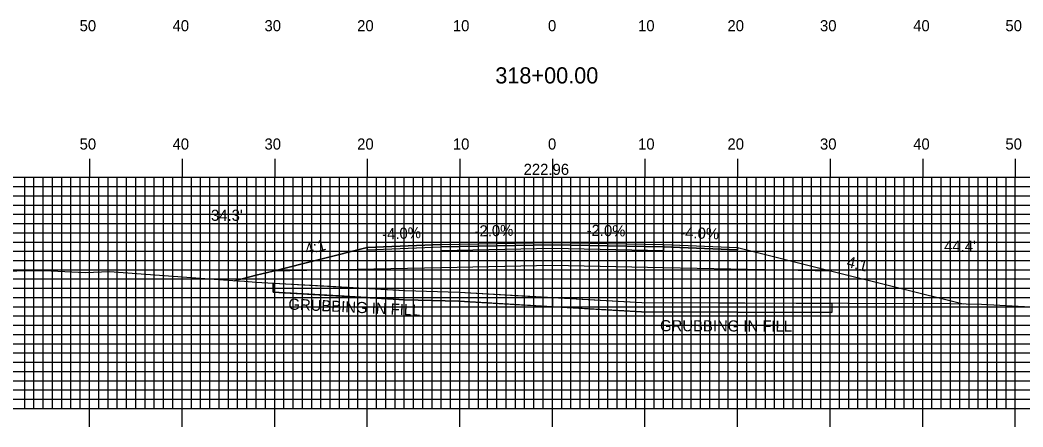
# Model space of a CAD drawing. Extents: x 1819637 to 1819981, y 442591 to 442811.
# Drawn here: x 1819745.7 to 1819854, y 442696.7 to 442740.7 of the extents above; entities that cross this region are included whole.
import ezdxf

# ---------------------------------------------------------------- set-up
doc = ezdxf.new("R2010")
doc.units = 0
for name, color, linetype in [('ANNOTATION', 7, 'Continuous'), ('D_Roadway_Centerline', 7, 'Continuous'), ('D_Roadway_Centerline_Text', 7, 'Continuous'), ('D_Roadway_Edge_Shoulder', 7, 'Continuous'), ('D_Roadway_Edge_TW', 7, 'Continuous'), ('D_Roadway_Pavement', 7, 'Continuous'), ('D_Roadway_SlopeLines', 7, 'Continuous'), ('D_Roadway_SubGrade', 7, 'Continuous'), ('D_Text_Standard', 7, 'Continuous'), ('GRUBBING IN FILL', 7, 'Continuous'), ('H_V ANNOTATION', 7, 'Continuous'), ('MAJOR', 7, 'Continuous'), ('MINOR', 7, 'Continuous'), ('S_Roadway_Centerline', 7, 'Continuous')]:
    doc.layers.add(name, color=color, linetype=linetype)

msp = doc.modelspace()

# ---------------------------------------------------------------- linework, layer by layer
at = {"layer": 'D_Roadway_Centerline'}
msp.add_lwpolyline([(1819768.84, 442712.48), (1819771.18, 442713.07), (1819773, 442713.52), (1819783.18, 442716.07), (1819791.18, 442716.39), (1819803.18, 442716.63), (1819815.18, 442716.39), (1819823.18, 442716.07), (1819833.35, 442713.52), (1819847.56, 442709.97)], dxfattribs=at)
at = {"layer": 'D_Roadway_Edge_Shoulder'}
for points in [[(1819791.18, 442716.39), (1819783.18, 442716.07), (1819783.18, 442715.82), (1819791.18, 442716.14)], [(1819815.18, 442716.39), (1819823.18, 442716.07), (1819823.18, 442715.82), (1819815.18, 442716.14)]]:
    msp.add_lwpolyline(points, close=True, dxfattribs=at)
at = {"layer": 'D_Roadway_Edge_TW'}
msp.add_lwpolyline([(1819791.18, 442716.14), (1819791.18, 442716.39), (1819803.18, 442716.63), (1819815.18, 442716.39), (1819815.18, 442716.14), (1819803.18, 442716.38)], close=True, dxfattribs=at)
at = {"layer": 'D_Roadway_Pavement'}
msp.add_lwpolyline([(1819791.18, 442715.72), (1819791.18, 442716.14), (1819803.18, 442716.38), (1819815.18, 442716.14), (1819815.18, 442715.72), (1819803.18, 442715.96)], close=True, dxfattribs=at)
at = {"layer": 'D_Roadway_SlopeLines'}
for points in [[(1819783.18, 442716.07), (1819773, 442713.52), (1819771.18, 442713.07), (1819768.84, 442712.48)], [(1819823.18, 442716.07), (1819833.35, 442713.52), (1819847.56, 442709.97)]]:
    msp.add_lwpolyline(points, dxfattribs=at)
at = {"layer": 'D_Roadway_SubGrade'}
msp.add_lwpolyline([(1819791.18, 442713.89), (1819773, 442713.52), (1819783.18, 442716.07), (1819783.18, 442715.82), (1819791.18, 442716.14), (1819803.18, 442716.38), (1819815.18, 442716.14), (1819823.18, 442715.82), (1819823.18, 442716.07), (1819833.35, 442713.52), (1819815.18, 442713.89), (1819803.18, 442714.13)], close=True, dxfattribs=at)
at = {"layer": 'GRUBBING IN FILL'}
for p, q in [((1819773, 442712.23), (1819773, 442711.23)), ((1819773, 442712.23), (1819773, 442711.23)), ((1819833.35, 442710.04), (1819833.35, 442709.04)), ((1819833.35, 442710.04), (1819833.35, 442709.04))]:
    msp.add_line(p, q, dxfattribs=at)
for points in [[(1819773, 442711.23), (1819773, 442712.23), (1819779.19, 442711.88), (1819787.25, 442711.42), (1819793.12, 442711.25), (1819802.98, 442710.68), (1819803.18, 442710.67), (1819803.18, 442709.67), (1819793.07, 442710.26), (1819787.21, 442710.42), (1819780.11, 442710.83)], [(1819773, 442711.23), (1819773, 442712.23), (1819779.19, 442711.88), (1819787.25, 442711.42), (1819793.12, 442711.25), (1819802.98, 442710.68), (1819803.18, 442710.67), (1819803.18, 442709.67), (1819793.07, 442710.26), (1819787.21, 442710.42), (1819780.11, 442710.83)], [(1819803.18, 442710.67), (1819812.84, 442710.11), (1819829.52, 442710.05), (1819833.35, 442710.04), (1819833.35, 442709.04), (1819823.08, 442709.08), (1819812.81, 442709.11), (1819803.18, 442709.67)], [(1819803.18, 442710.67), (1819812.84, 442710.11), (1819829.52, 442710.05), (1819833.35, 442710.04), (1819833.35, 442709.04), (1819823.08, 442709.08), (1819812.81, 442709.11), (1819803.18, 442709.67)]]:
    msp.add_lwpolyline(points, close=True, dxfattribs=at)
msp.add_lwpolyline([(1819773, 442711.23), (1819787.21, 442710.42), (1819793.07, 442710.26), (1819812.81, 442709.11), (1819833.35, 442709.04)], dxfattribs=at)
msp.add_lwpolyline([(1819773, 442711.23), (1819787.21, 442710.42), (1819793.07, 442710.26), (1819812.81, 442709.11), (1819833.35, 442709.04)], dxfattribs=at)
at = {"layer": 'MAJOR'}
for p, q in [((1819753.18, 442725.67), (1819753.18, 442723.67)), ((1819763.18, 442725.67), (1819763.18, 442723.67)), ((1819773.18, 442725.67), (1819773.18, 442723.67)), ((1819783.18, 442725.67), (1819783.18, 442723.67)), ((1819793.18, 442725.67), (1819793.18, 442723.67)), ((1819803.18, 442725.67), (1819803.18, 442723.67)), ((1819813.18, 442725.67), (1819813.18, 442723.67)), ((1819823.18, 442725.67), (1819823.18, 442723.67)), ((1819833.18, 442725.67), (1819833.18, 442723.67)), ((1819843.18, 442725.67), (1819843.18, 442723.67)), ((1819853.18, 442725.67), (1819853.18, 442723.67)), ((1819663.18, 442723.67), (1819943.18, 442723.67)), ((1819663.18, 442723.67), (1819943.18, 442723.67)), ((1819753.18, 442698.67), (1819753.18, 442723.67)), ((1819763.18, 442698.67), (1819763.18, 442723.67)), ((1819773.18, 442698.67), (1819773.18, 442723.67)), ((1819783.18, 442698.67), (1819783.18, 442723.67)), ((1819793.18, 442698.67), (1819793.18, 442723.67)), ((1819803.18, 442698.67), (1819803.18, 442723.67)), ((1819813.18, 442698.67), (1819813.18, 442723.67)), ((1819823.18, 442698.67), (1819823.18, 442723.67)), ((1819833.18, 442698.67), (1819833.18, 442723.67)), ((1819843.18, 442698.67), (1819843.18, 442723.67)), ((1819853.18, 442698.67), (1819853.18, 442723.67)), ((1819663.18, 442718.67), (1819943.18, 442718.67)), ((1819663.18, 442713.67), (1819943.18, 442713.67)), ((1819663.18, 442708.67), (1819943.18, 442708.67)), ((1819663.18, 442703.67), (1819943.18, 442703.67)), ((1819663.18, 442698.67), (1819943.18, 442698.67)), ((1819663.18, 442698.67), (1819943.18, 442698.67)), ((1819753.18, 442696.66), (1819753.18, 442698.67)), ((1819763.18, 442696.66), (1819763.18, 442698.67)), ((1819773.18, 442696.66), (1819773.18, 442698.67)), ((1819783.18, 442696.66), (1819783.18, 442698.67)), ((1819793.18, 442696.66), (1819793.18, 442698.67)), ((1819803.18, 442696.66), (1819803.18, 442698.67)), ((1819813.18, 442696.66), (1819813.18, 442698.67)), ((1819823.18, 442696.66), (1819823.18, 442698.67)), ((1819833.18, 442696.66), (1819833.18, 442698.67)), ((1819843.18, 442696.66), (1819843.18, 442698.67)), ((1819853.18, 442696.66), (1819853.18, 442698.67))]:
    msp.add_line(p, q, dxfattribs=at)
at = {"layer": 'MINOR'}
for p, q in [((1819746.18, 442698.67), (1819746.18, 442723.67)), ((1819747.18, 442698.67), (1819747.18, 442723.67)), ((1819748.18, 442698.67), (1819748.18, 442723.67)), ((1819749.18, 442698.67), (1819749.18, 442723.67)), ((1819750.18, 442698.67), (1819750.18, 442723.67)), ((1819751.18, 442698.67), (1819751.18, 442723.67)), ((1819752.18, 442698.67), (1819752.18, 442723.67)), ((1819754.18, 442698.67), (1819754.18, 442723.67)), ((1819755.18, 442698.67), (1819755.18, 442723.67)), ((1819756.18, 442698.67), (1819756.18, 442723.67)), ((1819757.18, 442698.67), (1819757.18, 442723.67)), ((1819758.18, 442698.67), (1819758.18, 442723.67)), ((1819759.18, 442698.67), (1819759.18, 442723.67)), ((1819760.18, 442698.67), (1819760.18, 442723.67)), ((1819761.18, 442698.67), (1819761.18, 442723.67)), ((1819762.18, 442698.67), (1819762.18, 442723.67)), ((1819764.18, 442698.67), (1819764.18, 442723.67)), ((1819765.18, 442698.67), (1819765.18, 442723.67)), ((1819766.18, 442698.67), (1819766.18, 442723.67)), ((1819767.18, 442698.67), (1819767.18, 442723.67)), ((1819768.18, 442698.67), (1819768.18, 442723.67)), ((1819769.18, 442698.67), (1819769.18, 442723.67)), ((1819770.18, 442698.67), (1819770.18, 442723.67)), ((1819771.18, 442698.67), (1819771.18, 442723.67)), ((1819772.18, 442698.67), (1819772.18, 442723.67)), ((1819774.18, 442698.67), (1819774.18, 442723.67)), ((1819775.18, 442698.67), (1819775.18, 442723.67)), ((1819776.18, 442698.67), (1819776.18, 442723.67)), ((1819777.18, 442698.67), (1819777.18, 442723.67)), ((1819778.18, 442698.67), (1819778.18, 442723.67)), ((1819779.18, 442698.67), (1819779.18, 442723.67)), ((1819780.18, 442698.67), (1819780.18, 442723.67)), ((1819781.18, 442698.67), (1819781.18, 442723.67)), ((1819782.18, 442698.67), (1819782.18, 442723.67)), ((1819784.18, 442698.67), (1819784.18, 442723.67)), ((1819785.18, 442698.67), (1819785.18, 442723.67)), ((1819786.18, 442698.67), (1819786.18, 442723.67)), ((1819787.18, 442698.67), (1819787.18, 442723.67)), ((1819788.18, 442698.67), (1819788.18, 442723.67)), ((1819789.18, 442698.67), (1819789.18, 442723.67)), ((1819790.18, 442698.67), (1819790.18, 442723.67)), ((1819791.18, 442698.67), (1819791.18, 442723.67)), ((1819792.18, 442698.67), (1819792.18, 442723.67)), ((1819794.18, 442698.67), (1819794.18, 442723.67)), ((1819795.18, 442698.67), (1819795.18, 442723.67)), ((1819796.18, 442698.67), (1819796.18, 442723.67)), ((1819797.18, 442698.67), (1819797.18, 442723.67)), ((1819798.18, 442698.67), (1819798.18, 442723.67)), ((1819799.18, 442698.67), (1819799.18, 442723.67)), ((1819800.18, 442698.67), (1819800.18, 442723.67)), ((1819801.18, 442698.67), (1819801.18, 442723.67)), ((1819802.18, 442698.67), (1819802.18, 442723.67)), ((1819804.18, 442698.67), (1819804.18, 442723.67)), ((1819805.18, 442698.67), (1819805.18, 442723.67)), ((1819806.18, 442698.67), (1819806.18, 442723.67)), ((1819807.18, 442698.67), (1819807.18, 442723.67)), ((1819808.18, 442698.67), (1819808.18, 442723.67)), ((1819809.18, 442698.67), (1819809.18, 442723.67)), ((1819810.18, 442698.67), (1819810.18, 442723.67)), ((1819811.18, 442698.67), (1819811.18, 442723.67)), ((1819812.18, 442698.67), (1819812.18, 442723.67)), ((1819814.18, 442698.67), (1819814.18, 442723.67)), ((1819815.18, 442698.67), (1819815.18, 442723.67)), ((1819816.18, 442698.67), (1819816.18, 442723.67)), ((1819817.18, 442698.67), (1819817.18, 442723.67)), ((1819818.18, 442698.67), (1819818.18, 442723.67)), ((1819819.18, 442698.67), (1819819.18, 442723.67)), ((1819820.18, 442698.67), (1819820.18, 442723.67)), ((1819821.18, 442698.67), (1819821.18, 442723.67)), ((1819822.18, 442698.67), (1819822.18, 442723.67)), ((1819824.18, 442698.67), (1819824.18, 442723.67)), ((1819825.18, 442698.67), (1819825.18, 442723.67)), ((1819826.18, 442698.67), (1819826.18, 442723.67)), ((1819827.18, 442698.67), (1819827.18, 442723.67)), ((1819828.18, 442698.67), (1819828.18, 442723.67)), ((1819829.18, 442698.67), (1819829.18, 442723.67)), ((1819830.18, 442698.67), (1819830.18, 442723.67)), ((1819831.18, 442698.67), (1819831.18, 442723.67)), ((1819832.18, 442698.67), (1819832.18, 442723.67)), ((1819834.18, 442698.67), (1819834.18, 442723.67)), ((1819835.18, 442698.67), (1819835.18, 442723.67)), ((1819836.18, 442698.67), (1819836.18, 442723.67)), ((1819837.18, 442698.67), (1819837.18, 442723.67)), ((1819838.18, 442698.67), (1819838.18, 442723.67)), ((1819839.18, 442698.67), (1819839.18, 442723.67)), ((1819840.18, 442698.67), (1819840.18, 442723.67)), ((1819841.18, 442698.67), (1819841.18, 442723.67)), ((1819842.18, 442698.67), (1819842.18, 442723.67)), ((1819844.18, 442698.67), (1819844.18, 442723.67)), ((1819845.18, 442698.67), (1819845.18, 442723.67)), ((1819846.18, 442698.67), (1819846.18, 442723.67)), ((1819847.18, 442698.67), (1819847.18, 442723.67)), ((1819848.18, 442698.67), (1819848.18, 442723.67)), ((1819849.18, 442698.67), (1819849.18, 442723.67)), ((1819850.18, 442698.67), (1819850.18, 442723.67)), ((1819851.18, 442698.67), (1819851.18, 442723.67)), ((1819852.18, 442698.67), (1819852.18, 442723.67)), ((1819663.18, 442722.67), (1819943.18, 442722.67)), ((1819663.18, 442721.67), (1819943.18, 442721.67)), ((1819663.18, 442720.67), (1819943.18, 442720.67)), ((1819663.18, 442719.67), (1819943.18, 442719.67)), ((1819663.18, 442717.67), (1819943.18, 442717.67)), ((1819663.18, 442716.67), (1819943.18, 442716.67)), ((1819663.18, 442715.67), (1819943.18, 442715.67)), ((1819663.18, 442714.67), (1819943.18, 442714.67)), ((1819663.18, 442712.67), (1819943.18, 442712.67)), ((1819663.18, 442711.67), (1819943.18, 442711.67)), ((1819663.18, 442710.67), (1819943.18, 442710.67)), ((1819663.18, 442709.67), (1819943.18, 442709.67)), ((1819663.18, 442707.67), (1819943.18, 442707.67)), ((1819663.18, 442706.67), (1819943.18, 442706.67)), ((1819663.18, 442705.67), (1819943.18, 442705.67)), ((1819663.18, 442704.67), (1819943.18, 442704.67)), ((1819663.18, 442702.67), (1819943.18, 442702.67)), ((1819663.18, 442701.67), (1819943.18, 442701.67)), ((1819663.18, 442700.67), (1819943.18, 442700.67)), ((1819663.18, 442699.67), (1819943.18, 442699.67))]:
    msp.add_line(p, q, dxfattribs=at)
at = {"layer": 'S_Roadway_Centerline'}
msp.add_lwpolyline([(1819663.18, 442715.35), (1819678.01, 442715.26), (1819687.76, 442714.98), (1819702.62, 442714.56), (1819702.72, 442714.55), (1819702.76, 442714.55), (1819718.24, 442714.82), (1819729.65, 442713.88), (1819736.46, 442713.45), (1819748.29, 442713.59), (1819752.75, 442713.37), (1819755.34, 442713.49), (1819766.13, 442712.68), (1819769.16, 442712.46), (1819769.93, 442712.42), (1819771.13, 442712.34), (1819787.25, 442711.42), (1819793.12, 442711.25), (1819812.84, 442710.11), (1819846.2, 442710), (1819849.54, 442709.93), (1819854.82, 442709.66)], dxfattribs=at)

# ---------------------------------------------------------------- texts
at = {"layer": 'ANNOTATION'}
for s, rotation, p in [('-4.0%', 2.2906, (1819784.81, 442716.93)), ('-2.0%', 1.1458, (1819794.78, 442717.26)), ('-2.0%', 358.8542, (1819806.86, 442717.35)), ('-4.0%', 357.7094, (1819816.97, 442717.12)), ('4:1', 14.0362, (1819776.63, 442715.29)), ('4:1', 345.9638, (1819834.88, 442714))]:
    msp.add_text(s, height=1.2, rotation=rotation, dxfattribs=at).set_placement(p)
at = {"layer": 'D_Roadway_Centerline'}
for s, p in [('C', (1819803.17, 442716.63)), ('L', (1819803.18, 442716.62))]:
    msp.add_text(s, height=0.0146, dxfattribs=at).set_placement(p)
at = {"layer": 'D_Roadway_Centerline_Text'}
msp.add_text('222.96', height=1.2, dxfattribs=at).set_placement((1819800.07, 442723.93))
at = {"layer": 'D_Text_Standard'}
for s, p in [("34.3'", (1819766.3, 442718.96)), ("44.4'", (1819845.49, 442715.63))]:
    msp.add_text(s, height=1.2, dxfattribs=at).set_placement(p)
at = {"layer": 'GRUBBING IN FILL'}
for rotation, p in [(357.22, (1819774.64, 442709.37)), (359.8053, (1819814.8, 442707.02))]:
    msp.add_text('GRUBBING IN FILL', height=1.2, rotation=rotation, dxfattribs=at).set_placement(p)
at = {"layer": 'H_V ANNOTATION'}
for s, height, p in [('50', 1.2, (1819752.11, 442739.47)), ('40', 1.2, (1819762.15, 442739.47)), ('30', 1.2, (1819772.08, 442739.47)), ('20', 1.2, (1819782.09, 442739.47)), ('10', 1.2, (1819792.43, 442739.47)), ('0', 1.2, (1819802.7, 442739.47)), ('10', 1.2, (1819812.43, 442739.47)), ('20', 1.2, (1819822.09, 442739.47)), ('30', 1.2, (1819832.08, 442739.47)), ('40', 1.2, (1819842.15, 442739.47)), ('50', 1.2, (1819852.11, 442739.47)), ('318+00.00', 1.75, (1819797.01, 442733.82)), ('50', 1.2, (1819752.11, 442726.67)), ('40', 1.2, (1819762.15, 442726.67)), ('30', 1.2, (1819772.08, 442726.67)), ('20', 1.2, (1819782.09, 442726.67)), ('10', 1.2, (1819792.43, 442726.67)), ('0', 1.2, (1819802.7, 442726.67)), ('10', 1.2, (1819812.43, 442726.67)), ('20', 1.2, (1819822.09, 442726.67)), ('30', 1.2, (1819832.08, 442726.67)), ('40', 1.2, (1819842.15, 442726.67)), ('50', 1.2, (1819852.11, 442726.67))]:
    msp.add_text(s, height=height, dxfattribs=at).set_placement(p)

doc.saveas('drawing.dxf')
